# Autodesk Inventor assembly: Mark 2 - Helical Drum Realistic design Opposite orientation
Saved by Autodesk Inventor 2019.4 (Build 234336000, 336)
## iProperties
Created: 2020-06
Part Number: Mark 2 - Helical Drum Realistic design Opposite orientation
Document SubType Name: Assembly
Designer: Administrator
Title: Mark 2 - Helical Drum Realistic design Opposite orientation v8
Author: Administrator
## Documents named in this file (5)
- c:\worker\convert-fusion-r04\tmp\job-1\412\output\files\42cd8afe-3a37-4067-aefe-abd8e56c7c1b\b979da8e-022f-4e16-895a-9769203428e9.iam
- c:\worker\convert-fusion-r04\tmp\job-1\412\output\files\42cd8afe-3a37-4067-aefe-abd8e56c7c1b\Component1.ipt
- c:\worker\convert-fusion-r04\tmp\job-1\412\output\files\42cd8afe-3a37-4067-aefe-abd8e56c7c1b\Component2.ipt
- c:\worker\convert-fusion-r04\tmp\job-1\412\output\files\42cd8afe-3a37-4067-aefe-abd8e56c7c1b\Component5.ipt
- c:\worker\convert-fusion-r04\tmp\job-1\412\output\files\42cd8afe-3a37-4067-aefe-abd8e56c7c1b\Mark 2 - Helical Drum Realistic design Opposite orientation v8.ipt
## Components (4 placed, 4 different names)
1. Component1:1
2. Component2:1
3. Component5:1
4. Mark 2 - Helical Drum Realistic design Opposite orientation v8
